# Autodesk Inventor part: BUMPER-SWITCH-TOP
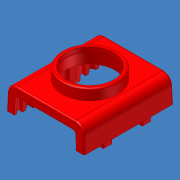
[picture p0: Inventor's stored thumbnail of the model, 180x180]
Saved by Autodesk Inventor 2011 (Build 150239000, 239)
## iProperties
Created: 2007-08
Part Number: BUMPER-SWITCH-TOP
Material: ABS Plastic
Document SubType Name: Modeling
Density: 1.06 g/cm^3
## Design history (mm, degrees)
feature "Base1"
body "Solid1"
